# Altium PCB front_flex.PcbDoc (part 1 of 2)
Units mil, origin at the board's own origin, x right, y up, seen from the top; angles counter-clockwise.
Board outline 5591.04 x 1020.3 mil, 4 copper layers (Layer 1 (Top Layer), Layer 2 (PWR), Layer 3 (GND), Layer 4 (Bottom Layer)), stack 21.036 mil thick; 26 components, 44 nets, 150 pads, 87 vias.
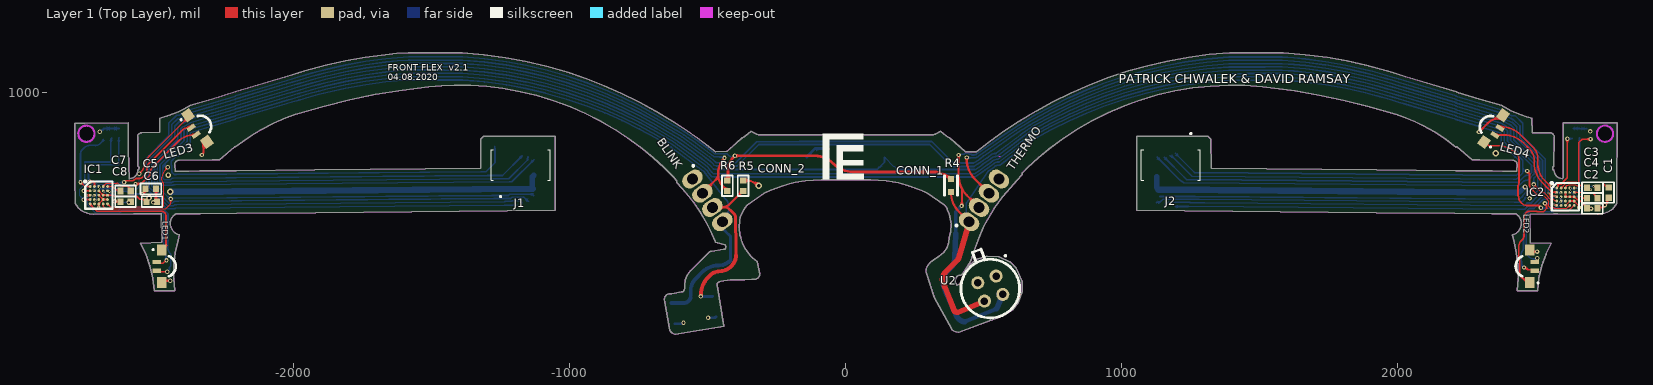
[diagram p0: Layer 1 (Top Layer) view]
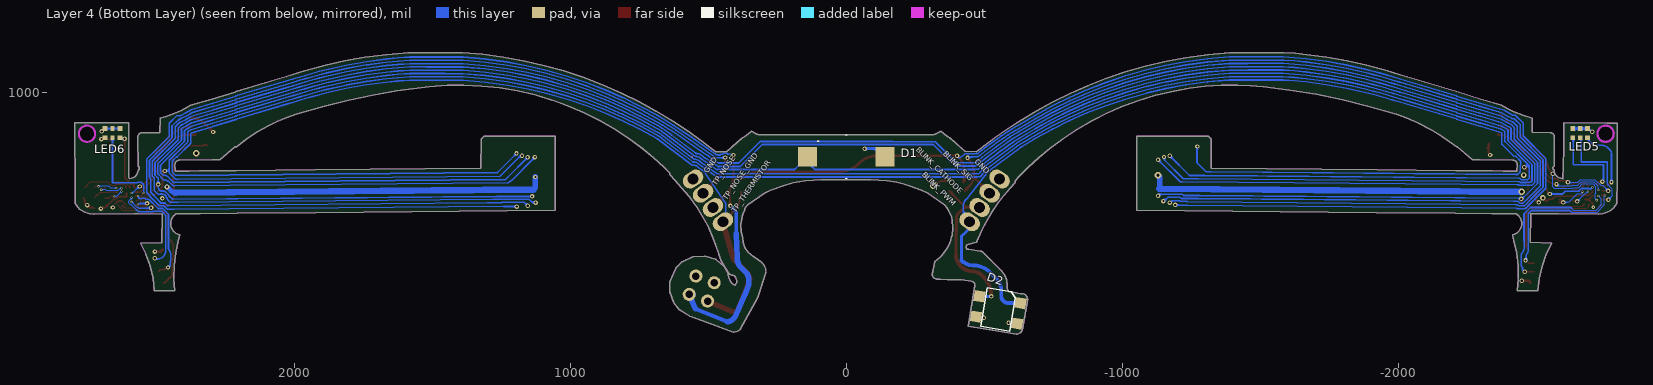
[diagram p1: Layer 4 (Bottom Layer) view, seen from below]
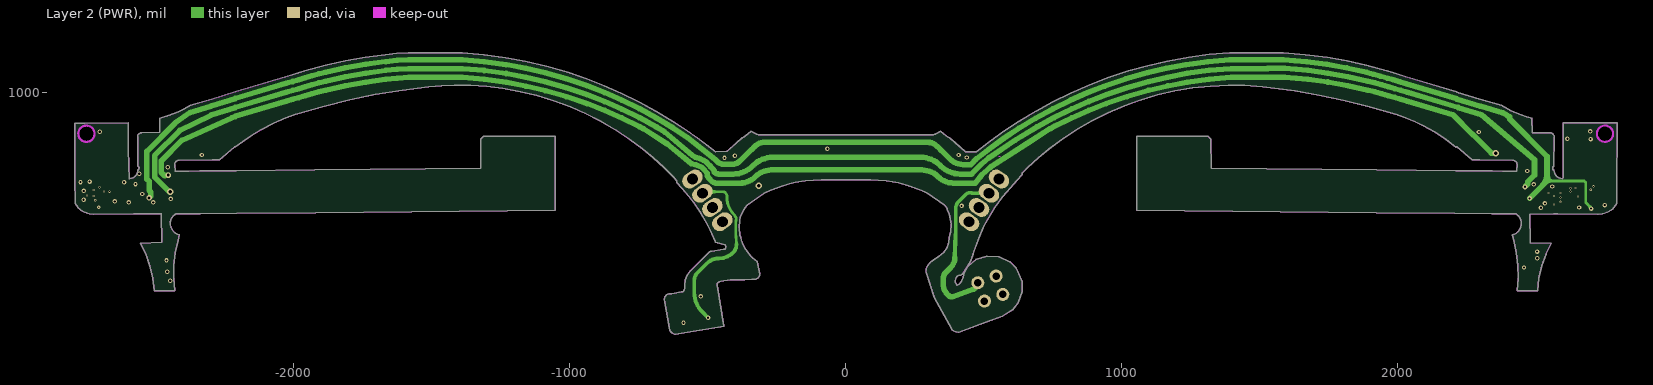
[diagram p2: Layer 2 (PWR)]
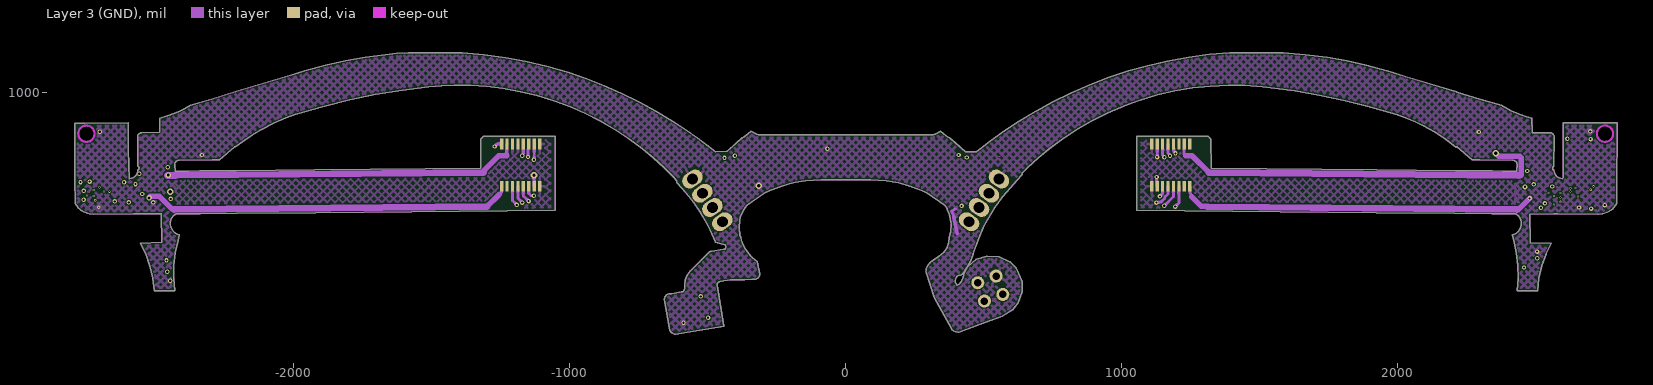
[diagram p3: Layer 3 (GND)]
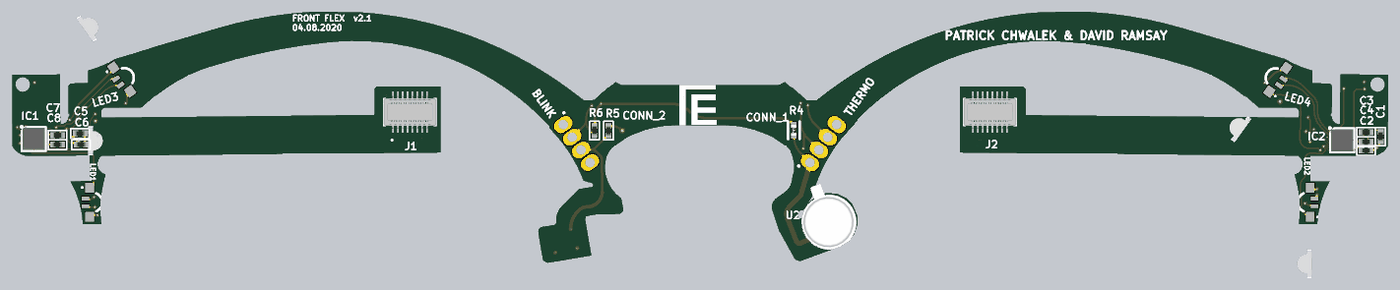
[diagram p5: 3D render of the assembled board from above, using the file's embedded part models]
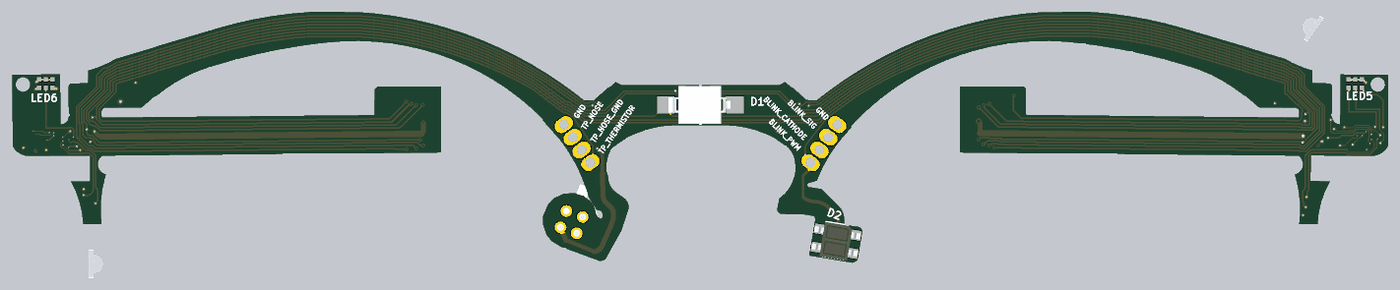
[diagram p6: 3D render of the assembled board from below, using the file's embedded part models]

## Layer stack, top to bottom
Top Solder: solder mask 1, SM-002, Dk 4
Layer 1 (Top Layer): signal copper 0.709
Dielectric 2: prepreg 2.8, PP-006, Dk 4.1
Layer 2 (PWR): signal copper 0.709
Dielectric 1: dielectric 12.6, FR-4, Dk 4.8
Layer 3 (GND): signal copper 0.709
Dielectric 3: prepreg 2.8, PP-006, Dk 4.1
Layer 4 (Bottom Layer): signal copper 0.709
Bottom Solder: solder mask 1, SM-002, Dk 4

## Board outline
570 vertices, not listed, extent -2794.4,125.06 2796.64,1145.35
cut-out: 2745.53,821.61 2750.93,820.83 2756.32,821.06 2761.63,822.28 2766.6,824.41 2771.08,827.44 2774.98,831.26 2778.09,835.71 2780.3,840.67 2781.6,845.91 2781.91,851.34 2781.24,856.73 2779.59,861.89 2777.03,866.65 2773.6,870.91 2769.47,874.41 2764.78,877.13 2762.11,878.23 2759.31,879.05 2753.92,879.8 2748.52,879.61 2743.21,878.39 2738.25,876.22 2733.76,873.19 2729.86,869.37 2726.75,864.92 2724.55,860 2723.25,854.72 2722.93,849.33 2723.6,843.94 2725.26,838.78 2727.82,833.98 2731.24,829.76 2735.38,826.22 2740.06,823.5 2742.74,822.44
cut-out: -2746.95,879.53 -2752.38,879.84 -2755.26,879.57 -2758.13,879.05 -2763.29,877.28 -2768.01,874.65 -2772.18,871.18 -2775.61,866.97 -2778.25,862.24 -2779.98,857.09 -2780.73,851.73 -2780.49,846.3 -2779.27,841.02 -2777.11,836.06 -2774.03,831.57 -2770.22,827.72 -2765.77,824.61 -2760.81,822.4 -2755.53,821.1 -2750.14,820.83 -2747.22,821.06 -2744.35,821.61 -2739.23,823.35 -2734.51,826.02 -2730.33,829.49 -2726.87,833.66 -2724.23,838.43 -2722.5,843.54 -2721.75,848.94 -2721.99,854.33 -2723.25,859.65 -2725.41,864.61 -2728.44,869.09 -2732.26,872.95 -2736.75,876.02 -2741.67,878.27
board region "Layer Stack Region 1": 534 vertices, not listed, extent -2794.4,125.06 2796.64,1145.35
board region "Layer Stack Region 1": -2424.82,715.71 -2380.81,716.14 -2341.51,716.5 -2209.43,717.72 -1923.84,720.31 -1323.01,726.93 -1322.62,728.31 -1322.62,832.13 -1311.87,842.87 -1053.36,843.15 -1053.36,573.35 -1920.92,565.39 -2206.48,562.76 -2340.1,561.53 -2379.43,561.18 -2423.37,560.78 -2425.18,560.77
board region "Layer Stack Region 1": 2429.51,560.75 2380.53,561.18 2341.28,561.53 2207.66,562.76 1922.11,565.39 1054.31,573.35 1054.31,842.87 1312.78,842.87 1323.53,831.85 1324.63,726.22 1326.04,725.79 1925.02,720.31 2210.57,717.72 2342.7,716.5 2382.03,716.14 2430.3,715.75 2432.23,715.74

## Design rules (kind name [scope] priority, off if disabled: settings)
Clearance [All] p1: gap=4 ignorepadtopadclearanceinfootprint=FALSE except(0: Arc-Hole Track-Hole SMDPad-Hole THPad-Hole Via-Hole Fill-Hole Poly-Hole Region-Hole Text-Hole)
DiffPairsRouting [All] p1: maxlimit=10 minlimit=10 mostfreqgap=10 toplayer_minwidth=15 toplayer_maxwidth=15 toplayer_prefwidth=15 midlayer1_minwidth=15 midlayer1_maxwidth=15 midlayer1_prefwidth=15 midlayer2_minwidth=15 midlayer2_maxwidth=15 midlayer2_prefwidth=15 bottomlayer_minwidth=15 bottomlayer_maxwidth=15 bottomlayer_prefwidth=15 substack1={A9119681-F30E-4965-AEFB-5FD7E99CBF57} toplayer_{a9119681-f30e-4965-aefb-5fd7e99cbf57}_minwidth=15 toplayer_{a9119681-f30e-4965-aefb-5fd7e99cbf57}_maxwidth=15 toplayer_{a9119681-f30e-4965-aefb-5fd7e99cbf57}_prefwidth=15 midlayer1_{a9119681-f30e-4965-aefb-5fd7e99cbf57}_minwidth=15 midlayer1_{a9119681-f30e-4965-aefb-5fd7e99cbf57}_maxwidth=15 midlayer1_{a9119681-f30e-4965-aefb-5fd7e99cbf57}_prefwidth=15 midlayer2_{a9119681-f30e-4965-aefb-5fd7e99cbf57}_minwidth=15 midlayer2_{a9119681-f30e-4965-aefb-5fd7e99cbf57}_maxwidth=15 midlayer2_{a9119681-f30e-4965-aefb-5fd7e99cbf57}_prefwidth=15 bottomlayer_{a9119681-f30e-4965-aefb-5fd7e99cbf57}_minwidth=15 bottomlayer_{a9119681-f30e-4965-aefb-5fd7e99cbf57}_maxwidth=15 bottomlayer_{a9119681-f30e-4965-aefb-5fd7e99cbf57}_prefwidth=15 substack2={F6C10761-EC22-4305-87DD-0F5299EFC78A} toplayer_{f6c10761-ec22-4305-87dd-0f5299efc78a}_minwidth=15 toplayer_{f6c10761-ec22-4305-87dd-0f5299efc78a}_maxwidth=15 toplayer_{f6c10761-ec22-4305-87dd-0f5299efc78a}_prefwidth=15 midlayer1_{f6c10761-ec22-4305-87dd-0f5299efc78a}_minwidth=15 midlayer1_{f6c10761-ec22-4305-87dd-0f5299efc78a}_maxwidth=15 midlayer1_{f6c10761-ec22-4305-87dd-0f5299efc78a}_prefwidth=15 midlayer2_{f6c10761-ec22-4305-87dd-0f5299efc78a}_minwidth=15 midlayer2_{f6c10761-ec22-4305-87dd-0f5299efc78a}_maxwidth=15 midlayer2_{f6c10761-ec22-4305-87dd-0f5299efc78a}_prefwidth=15 bottomlayer_{f6c10761-ec22-4305-87dd-0f5299efc78a}_minwidth=15 bottomlayer_{f6c10761-ec22-4305-87dd-0f5299efc78a}_maxwidth=15 bottomlayer_{f6c10761-ec22-4305-87dd-0f5299efc78a}_prefwidth=15 maxuncoupledlength=500
PlaneClearance [All] p1: clearance=8
PlaneConnect GND [InNet('GND')] p1: planeconnectstyle=Direct reliefexpansion=20 reliefentries=4 reliefconductorwidth=10 reliefairgap=10
PlaneConnect [All] p2: planeconnectstyle=Direct reliefexpansion=20 reliefentries=4 reliefconductorwidth=10 reliefairgap=10
PolygonConnect GND_1 [InNet('GND')] p1: thpad.connectstyle=Relief thpad.reliefconductorwidth=10 thpad.reliefentries=4 thpad.polygonreliefangle="90 Angle" thpad.airgapwidth=10 smdpad.connectstyle=Relief smdpad.reliefconductorwidth=10 smdpad.reliefentries=4 smdpad.polygonreliefangle="90 Angle" smdpad.airgapwidth=10 via.connectstyle=Direct via.reliefconductorwidth=10 via.reliefentries=4 via.polygonreliefangle="90 Angle" via.airgapwidth=10
PolygonConnect [All] p2: connectstyle=Relief reliefconductorwidth=10 reliefentries=4 polygonreliefangle="90 Angle" airgapwidth=10
RoutingCorners [All] p1: cornerstyle=Round minsetback=100 maxsetback=100
RoutingVias [All] p1: holewidth=8 width=16 viastyle="Through Hole" minholewidth=4 minwidth=8 maxholewidth=12 maxwidth=24
SolderMaskExpansion [All] p1: expansion=4 istentingtop=FALSE
Width POWER [InNet('3.3V') or InNet('5V') or InNet('BATTERY_1') or InNet('VBAT')] p1: maxlimit=30 minlimit=4 preferedwidth=20 toplayer_prefwidth=8 midlayer1_prefwidth=10 bottomlayer_prefwidth=8 substack1={A9119681-F30E-4965-AEFB-5FD7E99CBF57} substack2={F6C10761-EC22-4305-87DD-0F5299EFC78A} minimp=50.000000 maximp=50.000000 favimp=50.000000
Width [All] p2: maxlimit=10 minlimit=4 preferedwidth=10 toplayer_prefwidth=6 midlayer1_minwidth=10 midlayer2_minwidth=10 bottomlayer_prefwidth=6 substack1={A9119681-F30E-4965-AEFB-5FD7E99CBF57} substack2={F6C10761-EC22-4305-87DD-0F5299EFC78A} minimp=50.000000 maximp=50.000000 favimp=50.000000
26 further rules are at their usual default settings.

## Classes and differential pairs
component class Sch_led: C1 C2 C3 C4 C5 C6 C7 C8 IC1 IC2 J1 J2 LED1 LED2 LED3 LED4 LED5 LED6
component class Sch_front: CONN_1 CONN_2 D1 D2 R4 R5 R6 U2

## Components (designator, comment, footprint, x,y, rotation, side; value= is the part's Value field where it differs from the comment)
C1 "1µF" 0402R 2765.05,638.31 r90 top
C2 "1µF" 0402R 2706.02,581.51 r180 top
C3 "0.47µF" 0402R 2706.01,656.3 r180 top
C4 "0.47µF" 0402R 2706.02,616.93 r180 top
C5 "1µF" 0402R -2518.48,651.43 r180 top
C6 "1µF" 0402R -2514.43,605.63 r180 top
C7 "0.47µF" 0402R -2610.08,643.98 r0 top
C8 "0.47µF" 0402R -2610.08,605.63 r180 top
CONN_1 "THERMO" 4_POS_1MM_HEADER 501.25,610.02 r55 top
CONN_2 "BLINK" 4_POS_1MM_HEADER -501.25,610.02 r305 top
D1 "VBPW34FASR" VBPW34FAS 0,767.67 r180 bottom
D2 "QRE1113GR" *4LEADSMD_QRE1113GR(PRIMARY) -550.53,212.31 r9.5 bottom
IC1 "LP5523TM_NOPB" BGA25C40P5X5_226X226X68 -2706.84,628.81 r0 top
IC2 "LP5523TM_NOPB" BGA25C40P5X5_226X226X68 2608.64,623.29 r0 top
J1 "55560-0168" 555600168 -1178.04,737.95 r0 top
J2 "55560-0168" 555600168 1178.03,737.95 r180 top
LED1 "APFA3010SEKJ3ZGKQBKC" KPFA-3010RGBC-11 -2486.98,371.04 r90 top
LED2 "APFA3010SEKJ3ZGKQBKC" KPFA-3010RGBC-11 2486.98,371.04 r270 top
LED3 "APFA3010SEKJ3ZGKQBKC" KPFA-3010RGBC-11 -2355.09,866.3 r125.5 top
LED4 "APFA3010SEKJ3ZGKQBKC" KPFA-3010RGBC-11 2353.64,865.3 r234.5 top
LED5 "SMLP36RGB2W3R" ROHM-1510-(0604) -2659.41,853.66 r180 bottom
LED6 "SMLP36RGB2W3R" ROHM-1510-(0604) 2659.41,853.66 r180 bottom
R4 "100k" SMD-0402-RES 381.34,664.08 r180 top
R5 "100" 0402R -372.08,662.99 r270 top
R6 "51.1K" 0402R -428.65,662.99 r90 top
U2 "ZTP-135SR" ZTP-135SR 524.02,290.32 r335 top

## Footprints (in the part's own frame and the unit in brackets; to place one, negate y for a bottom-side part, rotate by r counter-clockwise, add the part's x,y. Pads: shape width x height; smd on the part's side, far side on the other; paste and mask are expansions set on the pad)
4_POS_1MM_HEADER [mm]
  oval 1.4x2 hole 1: 1(-2.4,0) 2(-0.8,0) 3(0.8,0) 4(2.4,0)
  silkscreen extent -3.4,0.7 -3.3,0.8
0402R [mm]
  rect 0.559x0.6 smd: 1(-0.48,0) 2(0.48,0)
  silkscreen extent -0.95,-0.5 0.95,0.5, body extent -0.46,-0.25 0.5,0.25, height 0.3
555600168 [mm]
  rect 0.3x1 on Mid1: 1(-1.75,-1.95) 2(-1.75,1.95) 3(-1.25,-1.95) 4(-1.25,1.95) 5(-0.75,-1.95) 6(-0.75,1.95) 7(-0.25,-1.95) 8(-0.25,1.95) 9(0.25,-1.95) 10(0.25,1.95) 11(0.75,-1.95) 12(0.75,1.95) 13(1.25,-1.95) 14(1.25,1.95) 15(1.75,-1.95) 16(1.75,1.95)
  silkscreen extent -2.73,-2.95 2.73,1.42, body extent -2.72,-2.15 2.73,2.15, height 1.16
*4LEADSMD_QRE1113GR(PRIMARY) [mm]
  rect 1x1 smd: A(-1.93,-0.97) C(1.93,0.94) E(-1.93,0.94) K(1.93,-0.97)
  silkscreen extent -1.35,-1.85 1.35,1.75, body extent -2.4,-1.8 2.4,1.8, height 1.85
BGA25C40P5X5_226X226X68 [mil]
  round 10 smd: A1(-31.5,31.5) A2(-15.75,31.5) A3(0,31.5) A4(15.75,31.5) A5(31.5,31.5) B1(-31.5,15.75) B2(-15.75,15.75) B3(0,15.75) B4(15.75,15.75) B5(31.5,15.75) C1(-31.5,0) C2(-15.75,0) C3(0,0) C4(15.75,0) C5(31.5,0) D1(-31.5,-15.75) D2(-15.75,-15.75) D3(0,-15.75) D4(15.75,-15.75) D5(31.5,-15.75) E1(-31.5,-31.5) E2(-15.75,-31.5) E3(0,-31.5) E4(15.75,-31.5) E5(31.5,-31.5)
  silkscreen extent -53,-49 49,53, body extent -44,-44 44,44, height 27
KPFA-3010RGBC-11 [mm]
  rect 1x0.9 smd: 1(1.5,-0.2) 2(-1.5,-0.2)
  rect 0.4x0.8 smd: 3(-0.4,0.25) 4(0.4,0.25)
  silkscreen extent -0.92,-1.5 1.54,0.59, body extent -1.36,-1.55 1.64,-0.05, height 1.02
ROHM-1510-(0604) [mm]
  rect 0.45x0.45 smd: 1(-0.675,-0.425) 3(0.675,-0.425) 4(0.675,0.425) 6(-0.675,0.425)
  rect 0.4x0.45 smd: 2(0,-0.425) 5(0,0.425)
SMD-0402-RES [mm]
  rect 0.55x0.55 smd: 1(0,0.584) 2(0,-0.584)
  silkscreen extent -0.6,-0.9 0.6,0.9, body extent -0.28,-0.57 0.27,0.58, height 0.41
VBPW34FAS [mm] "IR Photodiode SMD (Vive)"
  rect 1.75x1.8 smd: 1(-3.575,0) 2(3.575,0)
  silkscreen extent -2.65,-2 0.08,2, body extent -3.29,-1.95 3.11,1.95, height 1.48
ZTP-135SR [mm]
  round 1.2 hole 0.7: 1(0,1.27) 2(1.27,0) 3(0,-1.27) 4(-1.27,0)
  silkscreen extent -2.9,-2.7 2.7,3.35, body extent -3.24,-2.79 2.74,3.19, height 2.67

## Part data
C1 C2 C5 C6: library part GCM155C71A105KE38D, "CAP CER 1UF 10V X7S 0402", Digi-Key Part Number=490-13409-1-ND, Manufacturer="Murata Electronics North America", Operating Temperature="-55°C ~ 125°C", Package / Case="0402 (1005 Metric)", Ratings=AEC-Q200, Temperature Coefficient=X7S, Tolerance=±10%, Voltage=10V
C3 C4 C7 C8: library part GCM155C71A105KE38D, "CAP CER 0.47UF 10V X7S 0402", Digi-Key Part Number=490-13409-1-ND, Manufacturer="Murata Electronics North America", Operating Temperature="-55°C ~ 125°C", Package / Case="0402 (1005 Metric)", Ratings=AEC-Q200, Temperature Coefficient=X7S, Tolerance=±10%, Voltage=10V
CONN_1 CONN_2: library part 4_pin_1mm_header
D1: "Diode", Manufacturer_Name=Vishay, Mouser Part Number=782-VBPW34FASR, RS Part Number=7689401
D2: "QRE1113 Series 30 V 50 mA Miniature Reflective Object Sensor - SMD-4", Package="SMD-4 ON Semiconductor"
IC1 IC2: "Integrated Circuit", Manufacturer_Name="Texas Instruments", Manufacturer_Part_Number=LP5523TM/NOPB
J1 J2: "Connector", Manufacturer_Name=Molex, Mouser Part Number=538-55560-0168, RS Part Number=7206558P
LED1 LED2 LED3 LED4: "LED", Manufacturer_Name=Kingbright, Mouser Part Number=604-APFA3010SEKJ3ZGK
LED5 LED6: "LED", Manufacturer_Name="ROHM Semiconductor", Mouser Part Number=755-SMLP36RGB2W3R, RS Part Number=1246884
R4: library part ERJ-2GEJ104X, "RES SMD 100K OHM 5% 1/10W 0402", Digi-Key Part Number=P100KJCT-ND, Manufacturer="Panasonic Electronic Components", Operating Temperature="-55°C ~ 155°C", Package / Case="0402 (1005 Metric)", Power (Watts)="0.1W, 1/10W", Supplier Device Package=0402, Temperature Coefficient=±200ppm/°C, Tolerance=±5%
R5: library part Resistor
R6: library part Resistor, "CRCW040251K1FKED"
U2: "Undefined or Miscellaneous", Manufacturer_Name="Amphenol Advanced Sensors", Mouser Part Number=527-ZTP-135SR

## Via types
v1: diameter 16, hole 8, Layer 1 (Top Layer) to Layer 4 (Bottom Layer), tented both sides, 43 vias
v2: diameter 8, hole 4, Layer 1 (Top Layer) to Layer 4 (Bottom Layer), tented both sides, 19 vias
v3: diameter 16, hole 8, Layer 3 (GND) to Layer 4 (Bottom Layer), tented both sides, 17 vias
v4: diameter 24, hole 12, Layer 1 (Top Layer) to Layer 4 (Bottom Layer), tented both sides, 3 vias
v5: diameter 20, hole 10, Layer 1 (Top Layer) to Layer 4 (Bottom Layer), tented both sides, 2 vias
v6: diameter 18, hole 8, Layer 1 (Top Layer) to Layer 4 (Bottom Layer), tented both sides, 1 vias
v7: diameter 12, hole 6, Layer 1 (Top Layer) to Layer 4 (Bottom Layer), tented both sides, 1 vias
v8: diameter 24, hole 12, Layer 3 (GND) to Layer 4 (Bottom Layer), tented both sides, 1 vias

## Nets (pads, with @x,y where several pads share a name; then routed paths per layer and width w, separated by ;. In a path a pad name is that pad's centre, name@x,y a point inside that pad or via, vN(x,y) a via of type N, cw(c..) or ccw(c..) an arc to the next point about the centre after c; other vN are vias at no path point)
3.3V: J1.5 R4.2 R6.2 | length 4799
  Layer 1 (Top Layer) w10: R6.2@-428.65,681.89 ccw(c-434.31,687.55) -426.3,687.55 -426.3,719.92 cw(c-361.88,719.92) -407.44,765.47 v1(-401.49,771.42) -111.65,771.42 cw(c-111.65,677.91) -45.53,744.03 -44.07,742.57 ccw(c26.64,813.28) 26.64,713.28 318.08,713.28 cw(c318.08,623.82) R4.2@381.34,687.08 ; R6.2@-426.39,678.52 R6.2@-424.46,676.59
  Layer 3 (GND) w10: J1.5@-1207.57,661.18 -1207.57,609.07 v3(-1192.04,593.54)
  Layer 4 (Bottom Layer) w6: v3@-1192.04,591.99 -1192.89,592.84 -1236.74,592.84 -2430.07,581.9 -2430.21,581.9 -2431.91,580.19 -2444.01,580.19 -2444.51,579.69 -2460.74,579.69 -2475.35,594.3 -2534.88,653.83 -2534.88,761.79 -2452.92,843.75 -2452.92,890.28 -2424.96,918.24 -2415.31,918.24 -2384.45,936.57 -2296.29,962.47 -2212.03,987.84 -2212.05,989.31 -2027.38,1043.99 -2004.16,1050.86 -1981.48,1057.58 -1958.79,1064.3 -1934.04,1071.43 -1909.34,1078.15 -1884.54,1084.49 -1812.46,1100.67 -1739.75,1113.65 -1667.03,1123.33 -1624.87,1127.45 -1582.61,1130.47 -1520.87,1130.42 -1454.76,1130.33 -1388.64,1130.2 -1308.84,1123.29 -1229.5,1112.41 -1158.68,1099.25 -1088.65,1082.93 -1011.52,1061.06 -935.43,1035.32 -872.62,1010.82 -810.87,983.68 -747.3,952.45 -685.15,918.5 -624.51,881.9 -612.61,876.29 -581.43,857.37 -560.3,843.15 -534.44,824.28 -500.04,798.98 -479.44,782.4 -474.95,779.56 -462.07,778.39 -446.19,778.39 -445.52,779.06 -430.32,779.06 -422.65,771.39 -407.66,763.39
5V: J1.13 J2.14 | length 8474.4
  Layer 3 (GND) w10: v8(-1129.82,701.02) -1129.82,680.69 -1129.74,680.61 -1129.74,662.09 J1.13@-1128.83,661.18 ; v3(1126.77,694.87) 1126.77,681.72 1127.91,680.58 1127.91,662.09 J2.14@1128.82,661.18
  Layer 2 (PWR) w20: v4(-2447.81,640.97) -2451.37,640.97 -2504.88,694.49 -2504.88,771.99 -2413.25,863.62 -2300.83,918.33 -2300.54,918.42 ; -2296.79,919.87 -2212.54,945.24 -2212.55,946.71 -2027.88,1001.39 -2004.67,1008.27 -1981.98,1014.99 -1959.29,1021.71 -1934.54,1028.84 -1909.85,1035.55 -1885.04,1041.9 -1812.96,1058.07 -1740.25,1071.06 -1667.53,1080.74 -1625.37,1084.85 -1583.11,1087.87 -1521.37,1087.82 -1455.26,1087.74 -1389.14,1087.61 -1309.35,1080.7 -1230,1069.81 -1159.18,1056.65 -1089.15,1040.34 -1012.02,1018.46 -935.93,992.73 -873.12,968.22 -811.37,941.09 -747.8,909.86 -685.65,875.9 -655.33,857.6 -556.5,773.72 -544.91,766.19 -526.56,760.81 -517.02,756.2 -503.94,747.65 -491.02,734.73 cw(c-492.99,732.78) -490.22,732.78 -480.87,723.43 cw(c-492.15,712.14) -476.19,712.14 ccw(c-459.9,728.43) -459.9,705.39 -407.7,705.39 ccw(c-407.7,805.39) -336.99,734.68 -335.05,736.62 cw(c-264.34,665.91) -264.34,765.91 271.97,765.91 cw(c271.97,665.91) 342.68,736.62 344.72,734.58 ; 344.75,734.55 ccw(c414.87,804.73) 414.87,705.52 455.96,705.52 492.08,741.64 518.88,763.66 613.79,828.13 693.14,876.03 755.29,909.99 818.86,941.22 880.62,968.35 943.42,992.86 1019.52,1018.59 1096.65,1040.47 1166.68,1056.78 1237.5,1069.94 1316.84,1080.83 1396.64,1087.74 1462.75,1087.87 1528.87,1087.96 1590.61,1088 1632.87,1084.98 1675.03,1080.87 1747.74,1071.19 1820.45,1058.21 1892.54,1042.03 1917.34,1035.68 1942.04,1028.97 1966.79,1021.84 1989.48,1015.12 2012.16,1008.4 2035.37,1001.52 2220.04,946.84 2220.03,945.37 2304.29,920 2496.4,756.74 2496.4,701.92 2471.36,676.87 2471.36,668.85 v6@2464.72,662.21
  Layer 4 (Bottom Layer) w18: 2430.83,637.81 ccw(c2430.83,660.71) 2447.03,644.52 v6(2461.72,659.21)
  Layer 4 (Bottom Layer) w20: v4(-2447.81,640.97) -2438.32,640.97 v4@-2436.54,639.19 ; -1135.17,652.17 -1135.17,695.67 v8(-1129.82,701.02) ; v3(1126.77,694.87) 1126.77,690.21 1126.58,690.02 1126.58,657.15 1134.03,649.7
  Layer 4 (Bottom Layer) w25: v4@-2442.86,640.18 -1135.17,652.17 ; 1134.03,649.7 2430.83,637.81
BATTERY_1: J1.4 J2.3 | length 7986.3
  Layer 3 (GND) w10: v5@-2458.08,700.29 -2456.75,701.61 v5(-2455.44,701.61) ; -1228.81,771.84 -1228.81,794.65 -1228.16,795.3 -1228.16,813.82 J1.4@-1227.26,814.72 ; 1226.31,793.66 1226.31,777.34 1231.92,771.73
  Layer 3 (GND) w20: -1309.05,719.78 -1256.99,771.84 -1228.81,771.84 ; 1231.92,771.73 1254.59,771.73 1315.99,710.33 ; v4(2356.48,780.71) 2366.67,770.53 2442.16,770.53 2448.38,764.32 2448.38,702.31 2445.12,699.05
  Layer 3 (GND) w25: v5@-2458.08,700.29 -2428.97,700.29 ; -2422.55,701 -1312.36,711.18 ; 1315.99,710.33 2437.99,700.05
  Layer 2 (PWR) w20: v5(-2455.44,701.61) -2465.99,701.61 -2468.3,699.3 -2480.5,711.5 -2480.5,753.43 -2406.86,827.08 -2225.73,909.08 -2212.55,913.04 -2212.57,914.51 -2027.9,969.19 -2004.69,976.07 -1982,982.79 -1959.31,989.51 -1934.56,996.64 -1909.86,1003.35 -1885.06,1009.7 -1812.98,1025.88 -1740.27,1038.86 -1667.55,1048.54 -1625.39,1052.65 -1583.13,1055.67 -1521.39,1055.62 -1455.28,1055.54 -1389.16,1055.41 -1309.36,1048.5 -1230.02,1037.61 -1159.2,1024.45 -1089.17,1008.14 -1012.04,986.26 -935.95,960.53 -873.14,936.02 -811.39,908.89 -747.82,877.66 -732.28,869.17 -646.69,814.44 -558.92,742.19 -543.33,738.91 -519.08,728.85 -502.39,708.22 ccw(c-474.55,708.22) -494.24,688.53 -485.86,680.15 ccw(c-467.23,698.78) -467.23,672.44 -384.6,672.44 ccw(c-384.6,754.84) -326.33,696.57 cw(c-269.38,639.62) -269.38,720.16 275.78,720.16 cw(c275.78,636.68) 334.75,695.77 cw(c275.78,636.68) 334.82,695.71 ccw(c390.69,751.58) 390.69,672.57 469.98,672.57 493.33,702.12 525.19,730.93 654.19,814.57 739.77,869.3 755.31,877.79 818.88,909.02 880.64,936.15 943.44,960.66 1019.54,986.39 1096.67,1008.27 1166.7,1024.58 1237.52,1037.74 1316.86,1048.63 1396.66,1055.54 1462.77,1055.67 1528.88,1055.76 1590.62,1055.8 1632.88,1052.78 1675.04,1048.67 1747.76,1038.99 1820.47,1026.01 1892.56,1009.83 1917.36,1003.48 1942.06,996.77 1966.81,989.64 1989.49,982.92 2012.18,976.2 2035.39,969.32 2200.08,920.56 2270.47,850.17 ; 2272.91,849.59 2272.91,848.71 2340.14,781.48 2355.72,781.48 v4(2356.48,780.71)
BLINK_CATHODE: CONN_2.3 D2.K R5.2 | length 587.2
  Layer 1 (Top Layer) w4: CONN_2.3@-483.18,584.21 CONN_2.3@-448.37,584.21 ; R5.2@-374.11,643.25 cw(c-372.08,641.23) -373.07,643.92 cw(c-372.08,641.23) R5.2@-372.08,644.09
  Layer 1 (Top Layer) w8: CONN_2.3@-448.37,584.21 ccw(c-448.37,620.95) -436.24,586.27 ccw(c-448.37,620.95) -422.39,594.98 R5.2@-374.11,643.25
  Layer 1 (Top Layer) w10: v1(-525.03,261.81) v1@-525.03,265.74 ; -436.24,586.27 cw(c-457.05,534.75) -417.76,574.04 -403.54,559.83 cw(c-413.1,550.27) -399.58,550.27 -399.58,493.16 cw(c-405.24,487.51) -397.24,487.51 -397.24,411.02
  Layer 1 (Top Layer) w14: v1@-525.03,265.74 cw(c-430.11,265.74) -497.23,332.86 -492.01,338.09 cw(c-455.79,301.87) -455.79,353.09 ccw(c-455.79,406.73) -417.86,368.8 -412.52,374.14 ccw(c-449.4,411.02) -397.24,411.02
  Layer 4 (Bottom Layer) w10: v1(-525.03,261.81) -483.59,261.81 ccw(c-483.59,264.21) D2.K@-481.89,262.51
BLINK_PWM: CONN_2.4 D2.A J1.2 | length 4132.4
  Layer 1 (Top Layer) w6: CONN_2.4@-442.08,525.52 ccw(c-442.08,532.53) -437.13,527.57 CONN_2.4@-432.41,532.3
  Layer 3 (GND) w10: v3(-1272.3,805.2) -1262.78,814.72 J1.2@-1246.94,814.72
  Layer 4 (Bottom Layer) w6: -2375.27,853.83 -2375.27,811.97 -2378.2,811.97 -2420.87,769.3 -2426.87,769.3 -2444.26,751.91 -2444.26,738.68 -2442.09,736.51 -2442.09,716.8 ccw(c-2431.24,716.8) -2438.91,709.13 -2433.57,703.78 -2426.99,703.78 -1321.89,713.92 -1303.42,713.92 -1271.24,746.1 -1271.24,793.42 -1271.48,793.66 -1271.48,804.38 v3(-1272.3,805.2) ; -2375.27,855.33 -2298.01,878.29 -2297.73,878.37 ; -2296.29,878.47 -2212.03,903.84 -2212.05,905.31 -2027.38,959.99 -2004.16,966.86 -1981.48,973.58 -1958.79,980.3 -1934.04,987.43 -1909.34,994.15 -1884.54,1000.49 -1812.46,1016.67 -1739.75,1029.65 -1667.03,1039.33 -1624.87,1043.45 -1582.61,1046.47 -1520.87,1046.42 -1454.76,1046.33 -1388.64,1046.2 -1308.84,1039.29 -1229.5,1028.41 -1158.68,1015.25 -1088.65,998.93 -1011.52,977.06 -935.43,951.32 -872.62,926.82 -810.87,899.68 -747.3,868.45 -685.15,834.5 -633.35,803.23 -515,715.73 -435.84,615.43 cw(c-464.96,586.31) -423.78,586.31 -423.78,582.43 cw(c-487.88,582.43) CONN_2.4@-442.56,537.11 ; CONN_2.4@-436.79,520.99 -436.79,531.38 CONN_2.4@-415.14,553.03
  Layer 4 (Bottom Layer) w10: -562.56,256.5 ccw(c-588.5,264.26) -561.43,264.26 ; CONN_2.4@-447.05,532.61 -447.05,509.76 -436.96,499.66 ; -436.96,499.62 -417.4,480.06 -417.4,392.41
  Layer 4 (Bottom Layer) w14: D2.A@-631.78,237.43 -587.92,237.43 ccw(c-587.92,263.68) -569.35,245.12 ccw(c-588.5,264.26) -562.56,256.5 ; -561.43,264.26 -561.43,291.72 cw(c-495.16,279.4) -542.82,327.06 -519.94,349.94 cw(c-461.34,291.34) -461.34,374.21 ccw(c-461.34,436.36) -417.4,392.41
BLINK_SIG: CONN_2.2 D2.C J1.7 R6.1 | length 4748.1
  Layer 1 (Top Layer) w8: CONN_2.2@-519.31,635.82 -470.64,684.49 ccw(c-491.16,705.04) -462.12,705.04 ; v1(-439.31,764.06) ccw(c-384.24,708.99) -462.12,708.99 -462.12,705.04 ; R6.1@-428.65,644.09 -429.46,644.09 -438.46,653.09 -438.46,653.91 -445.49,660.93 cw(c-405.34,701.08) -462.12,701.08 -462.12,705.04
  Layer 3 (GND) w10: J1.7@-1187.89,661.18 -1187.89,617.67 v3(-1172.24,602.02)
  Layer 2 (PWR) w10: CONN_2.2@-519.31,635.82 cw(c-506.06,622.56) -506.06,641.31 -443.64,641.31 cw(c-443.64,631.09) -436.42,638.31 cw(c-451.01,623.72) -430.37,623.72 -430.37,621.25 ccw(c-342.13,621.25) -404.52,558.85 -404.61,558.77 cw(c-424.12,539.25) -396.52,539.25 -396.52,538.22 ccw(c-392.62,534.32) -398.14,534.32 -398.14,494.61 -395.89,449.75
  Layer 2 (PWR) w14: -502.08,382.18 -538.5,345.76 ccw(c-513.9,321.16) -548.69,321.16 -548.69,275.89 ccw(c-448.69,275.89) -519.4,205.18 v1(-498.66,184.43) ; -502.07,382.19 cw(c-459.88,339.98) -459.88,399.66 ccw(c-459.88,473.48) -407.69,421.28 ccw(c-436.16,449.75) -395.89,449.75
  Layer 4 (Bottom Layer) w6: -2297.73,950.37 -2298.01,950.29 -2375.27,927.33 -2393.36,916.85 -2412,907.34 -2413.04,906.3 -2420.57,906.3 -2442.09,884.78 -2442.09,840.44 -2524.88,757.64 -2524.88,657.97 -2513.73,646.82 -2504.49,637.57 -2456.6,589.69 -2456.1,590.19 -2436.05,590.19 -2431.68,594.57 -2424.27,594.57 -1235.74,605.47 -1234.2,607.01 -1209.55,607.01 -1208.26,608.31 -1198.48,608.31 -1198.25,608.54 -1180.99,608.54 -1174.48,602.02 v3(-1172.24,602.02) -1172.24,600.43 -1172.89,600.43 v3@-1173.36,600.91 ; -2296.29,950.47 -2212.03,975.84 -2212.05,977.31 -2027.38,1031.99 -2004.16,1038.86 -1981.48,1045.58 -1958.79,1052.3 -1934.04,1059.43 -1909.34,1066.15 -1884.54,1072.49 -1812.46,1088.67 -1739.75,1101.65 -1667.03,1111.33 -1624.87,1115.45 -1582.61,1118.47 -1520.87,1118.42 -1454.76,1118.33 -1388.64,1118.2 -1308.84,1111.29 -1229.5,1100.41 -1158.68,1087.25 -1088.65,1070.93 -1011.52,1049.06 -935.43,1023.32 -872.62,998.82 -810.87,971.68 -747.3,940.45 -685.15,906.5 -624.51,869.9 -614.19,864.37 -599.21,855.32 -585.74,847.02 -569.63,835.97 -551.73,823.87 -528.75,807.05 -502.31,787.12 -478.74,769.2 -458.79,767.27 v1@-442.39,767.14
  Layer 4 (Bottom Layer) w10: v1(-498.66,184.43) -478.95,184.43 ccw(c-478.95,197.81) D2.C@-469.48,188.35
EXPANSION_INT: J1.12 J2.11 | length 8291.9
  Layer 3 (GND) w10: v3(-1151.42,767.1) -1151.42,794.18 -1149.42,796.18 -1149.42,813.82 J1.12@-1148.52,814.72 ; J2.11@1148.5,814.72 1148.5,774.12 1155,767.62 v3(1155,766)
  Layer 4 (Bottom Layer) w6: -2297.73,902.37 -2298.01,902.29 -2375.27,879.33 -2393.36,868.85 -2398.09,864.12 -2398.09,826.36 -2484.88,739.57 -2484.88,679.45 -2480.73,675.3 -2467.31,675.3 -2466.62,674.61 -2443.04,674.61 -2439.56,678.1 -2436.42,678.1 -1276.47,688.62 -1220.64,688.62 -1153.14,756.13 -1153.14,762.56 -1150.62,765.07 -1150.62,766.31 v3(-1151.42,767.1) ; -2296.29,902.47 -2212.03,927.84 -2212.05,929.31 -2027.38,983.99 -2004.16,990.86 -1981.48,997.58 -1958.79,1004.3 -1934.04,1011.43 -1909.34,1018.15 -1884.54,1024.49 -1812.46,1040.67 -1739.75,1053.65 -1667.03,1063.33 -1624.87,1067.45 -1582.61,1070.47 -1520.87,1070.42 -1454.76,1070.33 -1388.64,1070.2 -1308.84,1063.29 -1229.5,1052.41 -1158.68,1039.25 -1088.65,1022.93 -1011.52,1001.06 -935.43,975.32 -872.62,950.82 -810.87,923.68 -747.3,892.45 -685.15,858.5 -624.51,821.9 -617.18,817.07 -509.59,738.46 -499.2,729.45 -494.01,723.42 -484.79,711.31 -479.4,705.92 -468.69,706.03 467.53,706.03 486.5,719.59 508.54,734.91 527.35,748.72 527.93,749.3 cw(c551.95,725.28) 551.95,759.25 655,837.18 664.91,844.49 670.27,848.66 673.34,851.07 684.89,857.72 747.04,891.68 810.61,922.91 872.36,950.04 935.17,974.55 1011.26,1000.28 1088.39,1022.16 1158.42,1038.47 1229.24,1051.63 1308.58,1062.51 1388.38,1069.42 1454.5,1069.56 1520.61,1069.64 1582.35,1069.69 1624.61,1066.67 1666.77,1062.56 1739.49,1052.88 1812.2,1039.89 1884.28,1023.71 1909.08,1017.37 1933.78,1010.66 1958.53,1003.53 1981.22,996.81 2003.91,990.08 2027.12,983.21 2211.79,928.53 2211.77,927.06 2296.03,901.69 ; v3(1155,766) 1228.02,692.98 1235.37,685.49 2434.22,674.61 ccw(c2434.22,683.38) 2440.42,677.18 2459.8,696.56 cw(c2470.15,686.21) 2470.15,700.85 ccw(c2470.15,714.77) 2480,704.93 2485.38,710.3 2485.38,737.62 2398.62,824.38 2398.62,862.13 2393.89,866.86 2375.8,877.34 ; 2296.26,901.39 2296.55,901.3 2373.8,878.34
GND: C1.1 C2.1 C5.1 C6.1 CONN_1.4 CONN_2.1 D1.2 D2.E IC1.C3 IC1.D4 IC1.D5 IC1.E3 IC2.D4 IC2.D5 IC2.E3 J1.6 J1.8 J1.15 J1.16 J2.15 J2.16 LED1.2 LED2.2 LED3.2 LED4.2 LED5.4 LED5.5 LED5.6 LED6.4 LED6.5 LED6.6 R5.1 U2.1 | length 868.6
  Layer 1 (Top Layer) w4: v7(-2706.96,585.42) -2706.96,597.18 -2706.84,597.3 IC1.D4@-2691.09,613.06 IC1.D5@-2675.34,613.06 ; IC1.C3@-2706.75,628.91 -2706.75,628.72 -2691.88,613.85 IC1.D4@-2691,613.85 ; LED1.2@-2481,310.09 -2478.75,307.83 LED1.2@-2475.93,307.83 ; R5.1@-372.08,681.89 R5.1@-361.14,681.89 ; LED2.2@2473.75,428.37 LED2.2@2475.56,426.56 ; IC2.E3@2608.62,591.81 2608.62,592.99 2610.79,595.16 2612.18,596.55 2613.19,596.55 2619.64,602.99 2619.64,604.01 2623.19,607.56 IC2.D5@2640.13,607.55 ; IC2.D5@2640.13,607.55 2655.83,591.85 2655.83,586.37 v1(2658.13,584.07)
  Layer 1 (Top Layer) w6: v1@-2510.44,602.72 v1@-2507.53,605.63 ; v1(-2509.54,602.72) v1@-2509.54,603.62 ; C6.1@-2499.58,605.69 -2499.53,605.63 C6.1@-2498.6,606.56 ; C2.1@2724.92,581.51 2730.97,584.16 2741.89,584.16 v1(2750.76,593.03) 2753.47,593.03 2757.89,597.45 2758.39,597.45 2759.88,598.94 2759.88,614.25 C1.1@2765.05,619.42
  Layer 1 (Top Layer) w8: C6.1@-2499.58,605.69 C5.1@-2499.58,651.43 ; v1(-2333.09,774.3) -2333.09,777.04 -2327.49,782.64 LED3.2@-2327.49,813.5 ; R5.1@-361.14,681.89 cw(c-361.14,617.37) v4(-315.51,662.99) ; v1(2294.91,857.82) 2326.66,889.57 cw(c2370.99,845.24) LED4.2@2370.99,907.93
  Layer 1 (Top Layer) w10: LED1.2@-2479.1,311.99 -2478.95,311.99 -2471.84,319.1 -2471.72,318.97 -2448,318.97 v1(-2447.81,318.78) ; LED2.2@2479.1,430.1 2484.97,424.23 v1(2505.87,424.23)
  Layer 3 (GND) w10: 392.46,549.45 384.04,571.02 397.67,579.26
  Layer 3 (GND) w13: 392.46,549.45 403.77,488.61
  Layer 4 (Bottom Layer) w6: LED6.4@2636.76,870.39 LED6.5@2659.41,870.39 ; LED6.5@2662.87,870.18 2685.17,870.18 2685.52,869.83 2685.98,870.3 LED6.6@2685.98,870.39
  Layer 4 (Bottom Layer) w8: v1(-2703.42,858.47) -2702.42,858.47 -2695.55,865.34 -2692.86,865.34 -2688,870.2 LED5.6@-2634.85,870.2
  Layer 4 (Bottom Layer) w10: D2.E@-619.37,163.27 -596.53,163.27 ccw(c-596.53,173.24) -589.48,166.19 cw(c-588.54,165.25) -588.54,166.58 v1(-587.92,166.58) ; D1.2@-140.75,767.67 -140.75,768.25 -111.3,797.7 -66.86,797.7 v1(-66.26,797.09)
  other v1: 2698.42,860.08
I2C_SCL: IC1.E5 IC2.E5 J1.10 J2.9 | length 8801.1
  Layer 1 (Top Layer) w4: IC1.E5@-2675.34,597.3 -2665.33,587.3 -2486.9,587.3 -2486.56,587.64 -2474.64,587.64 -2470.95,591.33 -2470.95,666.06 ccw(c-2482.64,666.06) -2474.37,674.33 cw(c-2463.22,685.48) -2478.99,685.48 -2478.99,693.13 cw(c-2396.15,669.36) v1(-2457.09,730.3) ; 2513.54,629.26 2526.97,629.26 2537.49,618.74 2537.49,618.61 2548.7,607.4 2548.7,588.02 2564.08,572.64 2619.77,572.64 2627.93,580.8 2628.94,580.8 2635.38,587.24 2635.38,588.26 2638.94,591.81 IC2.E5@2640.12,591.81
  Layer 1 (Top Layer) w6: v1(2470.38,716.52) ccw(c2476.46,716.52) 2472.16,712.21 2478.11,706.26 2478.11,665.71 ccw(c2494.66,665.71) 2482.95,654.01 2503.57,633.4 ccw(c2513.54,643.37) 2513.54,629.26
  Layer 3 (GND) w10: v3(-1172.25,771.73) -1172.25,773.35 -1168.2,777.4 J1.10@-1168.2,814.72 ; J2.9@1168.19,814.72 1168.19,780.51 1175.35,773.35 v3(1175.35,771.73)
  Layer 4 (Bottom Layer) w6: v1@-2459.79,730.3 -2464.92,735.43 -2474.88,735.43 ; -2297.73,890.37 -2298.01,890.29 -2375.27,867.33 -2386.42,860.87 -2386.42,823.12 -2387.19,823.12 -2474.88,735.43 ; -2296.29,890.47 -2212.03,915.84 -2212.05,917.31 -2027.38,971.99 -2004.16,978.86 -1981.48,985.58 -1958.79,992.3 -1934.04,999.43 -1909.34,1006.15 -1884.54,1012.49 -1812.46,1028.67 -1739.75,1041.65 -1667.03,1051.33 -1624.87,1055.45 -1582.61,1058.47 -1520.87,1058.42 -1454.76,1058.33 -1388.64,1058.2 -1308.84,1051.29 -1229.5,1040.41 -1158.68,1027.25 -1088.65,1010.93 -1011.52,989.06 -935.43,963.32 -872.62,938.82 -810.87,911.68 -747.3,880.45 -685.15,846.5 -624.51,809.9 -510.51,725.59 -501.89,717.16 -495.65,708.03 -484.87,695.5 -474.2,694.7 469.14,694.7 469.65,695.2 491.17,710.08 534.11,740.93 cw(c554,721.04) 554,749.16 555.58,749.16 654.81,824.28 678.08,841.93 680.91,842.95 684.89,845.72 747.04,879.68 810.61,910.91 872.36,938.04 935.17,962.55 1011.26,988.28 1088.39,1010.16 1158.42,1026.47 1229.24,1039.63 1308.58,1050.51 1388.38,1057.42 1454.5,1057.56 1520.61,1057.64 1582.35,1057.69 1624.61,1054.67 1666.77,1050.56 1739.49,1040.88 1812.2,1027.89 1884.28,1011.71 1909.08,1005.37 1933.78,998.66 1958.53,991.53 1981.22,984.81 2003.91,978.08 2027.12,971.21 2211.79,916.53 2211.77,915.06 2296.03,889.69 ; v3(-1172.25,771.73) -1243.65,700.32 -1298.42,700.32 -2436.49,689.89 -2441.91,689.89 -2447.18,684.61 -2462.48,684.61 -2463.16,685.3 -2469.11,685.3 -2474.88,691.07 -2474.88,735.43 ; v3(1175.35,771.73) 1177.26,769.82 1182.45,769.82 1255.06,697.22 2420.56,686.53 2425.72,686.53 ccw(c2425.72,699.22) 2434.7,690.25 2453.4,708.95 2453.4,717.42 2453.62,717.64 ; 2296.26,889.39 2296.55,889.3 2373.8,866.34 ; 2375.8,865.34 2386.95,858.88 2386.95,821.64 2431.28,777.31 2431.54,777.31 2453.62,755.23 2453.62,717.64 ; v1(2470.38,716.52) 2469.25,717.64 2453.62,717.64
I2C_SDA: IC1.E4 IC2.E4 J1.11 J2.12 | length 8977.7
  Layer 1 (Top Layer) w4: IC1.E4@-2691.09,597.31 -2691.09,589.06 -2681.32,579.3 -2483.58,579.3 -2483.24,579.64 -2463.73,579.64 -2446.41,596.96 v1(-2446.41,615.19) ; v1(2493.36,667.76) 2519.52,641.6 ccw(c2525.71,647.79) 2525.71,639.03 cw(c2525.71,628.32) 2533.29,635.9 2544.24,624.95 cw(c2541.22,621.93) 2545.49,622.06 cw(c2541.22,621.93) 2545.49,621.93 2556.7,610.72 2556.7,591.34 2567.4,580.64 2613.25,580.64 IC2.E4@2624.38,591.8 IC2.E4@2624.37,591.81
  Layer 3 (GND) w10: J1.11@-1148.52,661.18 -1148.27,660.94 -1148.27,634.62 -1140.68,627.02 v3(-1130.02,627.02) ; v3(1138.93,624.27) 1148.5,633.85 J2.12@1148.5,661.18
  Layer 4 (Bottom Layer) w6: v1@-2448.96,615.24 -2504.88,671.17 -2504.88,747.85 -2421.09,831.65 -2421.09,874.25 -2412,883.34 -2393.36,892.85 -2375.27,903.33 -2298.01,926.29 -2297.73,926.37 ; v1(-2446.41,615.19) -2446.41,615.4 -2444.65,617.16 -2435.72,617.16 -1282.57,627.63 -1220.65,627.63 -1220.65,629.38 -1218.2,631.84 -1209,631.92 -1201.01,631.99 ; -2296.29,926.47 -2212.03,951.84 -2212.05,953.31 -2027.38,1007.99 -2004.16,1014.86 -1981.48,1021.58 -1958.79,1028.3 -1934.04,1035.43 -1909.34,1042.15 -1884.54,1048.49 -1812.46,1064.67 -1739.75,1077.65 -1667.03,1087.33 -1624.87,1091.45 -1582.61,1094.47 -1520.87,1094.42 -1454.76,1094.33 -1388.64,1094.2 -1308.84,1087.29 -1229.5,1076.41 -1158.68,1063.25 -1088.65,1046.93 -1011.52,1025.06 -935.43,999.32 -872.62,974.82 -810.87,947.68 -747.3,916.45 -685.15,882.5 -624.51,845.9 -599.64,831.18 -570.65,810.7 -526.68,779.34 -491.01,752.29 -481.74,743.89 -477.21,737.85 -469.67,734.79 -393.65,734.39 -315.65,812.39 304.62,812.39 384.16,732.85 465.34,732.85 485.75,745.94 511.86,763.79 517.24,766.89 520.23,769.87 cw(c544.93,745.16) 544.93,780.1 633.56,846.87 638.4,850.97 651.22,860.8 659.19,866.53 664.18,869.2 668.58,871.77 669.8,872.68 684.89,881.72 747.04,915.68 810.61,946.91 872.36,974.04 935.17,998.55 1011.26,1024.28 1088.39,1046.16 1158.42,1062.47 1229.24,1075.63 1308.58,1086.51 1388.38,1093.42 1454.5,1093.56 1520.61,1093.64 1582.35,1093.69 1624.61,1090.67 1666.77,1086.56 1739.49,1076.88 1812.2,1063.89 1884.28,1047.71 1909.08,1041.37 1933.78,1034.66 1958.53,1027.53 1981.22,1020.81 2003.91,1014.08 2027.12,1007.21 2211.79,952.53 2211.77,951.06 2296.03,925.69 ; -1209,631.99 -1201.01,631.99 ; v3(-1130.02,627.02) -1135.59,632.59 -1201.01,631.99 ; v3(1138.93,624.27) 1266.24,624.27 2441.52,613.6 2448.98,621.05 2450.04,621.05 2453.6,624.62 2453.6,627.58 2468.25,642.22 2469.88,642.22 ; 2296.26,925.39 2296.55,925.3 2373.8,902.34 ; 2375.8,901.34 2393.89,890.86 2412.53,881.35 2421.62,872.26 2421.62,829.66 2505.38,745.9 2505.38,702.02 2493.36,690 v1(2493.36,667.76) 2493.36,658.4 cw(c2475.57,658.4) 2488.15,645.82 cw(c2483.65,650.32) 2483.65,643.96 2475.03,643.96 ccw(c2475.03,635.44) 2469.88,642.22 ; 2469.01,641.46 cw(c2475.03,635.44) 2469.88,642.22
IMU_INT: J1.9 J2.10 | length 8642
  Layer 3 (GND) w10: J1.9@-1168.2,661.18 -1168.2,626.27 v3(-1149.34,607.41) ; v3(1126.26,602) 1127.4,603.15 1141.85,603.15 1155.93,617.23 1155.93,621.23 1168.19,633.5 J2.10@1168.19,661.18
  Layer 4 (Bottom Layer) w6: -2297.73,938.37 -2298.01,938.29 -2375.27,915.33 -2393.36,904.85 -2412,895.34 -2415.05,895.34 -2432.09,878.3 -2432.09,836.3 -2514.88,753.5 -2514.88,662.12 -2453,600.23 -2452.67,600.23 -2452.62,600.19 -2440.2,600.19 -2433.74,606.65 -2416.99,606.65 -1275.71,617.01 -1213.7,617.01 -1208.96,621.75 ; -2296.29,938.47 -2212.03,963.84 -2212.05,965.31 -2027.38,1019.99 -2004.16,1026.86 -1981.48,1033.58 -1958.79,1040.3 -1934.04,1047.43 -1909.34,1054.15 -1884.54,1060.49 -1812.46,1076.67 -1739.75,1089.65 -1667.03,1099.33 -1624.87,1103.45 -1582.61,1106.47 -1520.87,1106.42 -1454.76,1106.33 -1388.64,1106.2 -1308.84,1099.29 -1229.5,1088.41 -1158.68,1075.25 -1088.65,1058.93 -1011.52,1037.06 -935.43,1011.32 -872.62,986.82 -810.87,959.68 -747.3,928.45 -685.15,894.5 -624.51,857.9 -593.5,839.8 -544.25,804.99 -493.27,767.27 -479.05,755.42 -469.65,746.39 -398.65,746.39 -322.65,822.39 -168.61,822.39 -167.41,823.6 312.41,823.6 390.39,745.61 464.25,745.61 465.02,746.38 481.68,756.02 500.68,771.23 526.51,788.69 608.66,846.53 616.72,851.98 629.32,859.97 652.02,873.85 658.47,878.09 667.91,883.45 684.89,893.72 747.04,927.68 810.61,958.91 872.36,986.04 935.17,1010.55 1011.26,1036.28 1088.39,1058.16 1158.42,1074.47 1229.24,1087.63 1308.58,1098.51 1388.38,1105.42 1454.5,1105.56 1520.61,1105.64 1582.35,1105.69 1624.61,1102.67 1666.77,1098.56 1739.49,1088.88 1812.2,1075.89 1884.28,1059.71 1909.08,1053.37 1933.78,1046.66 1958.53,1039.53 1981.22,1032.81 2003.91,1026.08 2027.12,1019.21 2211.79,964.53 2211.77,963.06 2296.03,937.69 ; -1208.96,621.88 -1166.91,622.27 -1152.05,607.41 v3(-1149.34,607.41) ; v3(1126.26,602) 1127.06,602.8 1138.67,602.8 1150.14,614.27 1262.1,614.27 1262.92,613.45 1281.51,613.45 2422.79,603.09 2444.31,603.09 ccw(c2444.31,616.94) 2454.1,607.14 2459.55,612.59 ccw(c2453.54,618.59) 2462.03,618.59 2463.97,620.53 cw(c2471.84,620.53) 2466.27,626.09 2467.6,627.42 ; 2296.26,937.39 2296.55,937.3 2373.8,914.34 ; 2375.8,913.34 2393.89,902.86 2412.53,893.35 2415.58,893.35 2432.62,876.31 2432.62,834.31 2515.38,751.56 2515.38,697.88 2508.36,690.86 2508.36,646.1 2507.29,645.03 2507.29,644.76 2495.32,632.78 2485.44,632.78 2485.35,632.87 2479.63,632.87 ccw(c2479.63,620.15) 2473.66,631.38 ccw(c2473.66,626.34) 2470.09,629.9 2468.41,628.22
LED_LEFT_FRONT_B: IC1.A1 LED5.3 | length 254.9
  Layer 1 (Top Layer) w4: v1(-2773.09,676.3) -2757.09,660.3 IC1.A1@-2738.33,660.3
  Layer 4 (Bottom Layer) w6: v1(-2773.09,676.3) -2773.09,781.27 ; -2772.98,781.27 cw(c-2758.68,781.27) -2768.79,791.38 -2759.6,800.57 cw(c-2738.7,779.68) -2738.7,809.22 -2738.7,809.3 -2720.07,809.3 ; LED5.3@-2691.34,830.5 cw(c-2701.43,830.5) -2694.3,823.36 -2700.5,817.15 cw(c-2720.07,836.73) -2716.36,809.3 ; -2720.07,809.3 -2716.36,809.3 ; -2720.07,809.3 -2720.07,809.05 ccw(c-2720.07,836.73) -2716.36,809.3
LED_LEFT_FRONT_G: IC1.A2 LED5.1 | length 308.2
  Layer 1 (Top Layer) w4: IC1.A2@-2722.58,660.3 -2722.58,673.55
  Layer 1 (Top Layer) w6: v1(-2740.11,678.11) -2727.15,678.11 -2722.58,673.55
  Layer 4 (Bottom Layer) w6: v1(-2740.11,678.11) -2743.45,678.11 -2744.09,677.47 -2744.09,739.3 -2634.51,739.3 -2634.51,823.56 ; -2634.29,822.74 -2634.29,836.93 LED5.1@-2632.84,836.93
LED_LEFT_FRONT_R: IC1.D1 LED5.2 | length 357.4
  Layer 1 (Top Layer) w4: v1(-2762.09,612.3) -2761.33,613.05 IC1.D1@-2738.33,613.06
  Layer 4 (Bottom Layer) w4: v1(-2762.09,612.3) -2776.09,626.3 -2776.09,650.51 -2759.09,667.51
  Layer 4 (Bottom Layer) w6: -2759.09,667.51 -2759.09,669.08 -2758.09,670.08 -2758.09,749.3 -2663.09,749.3 -2663.09,832.56 LED5.2@-2663.54,832.56 ; LED5.2@-2659.41,832.56 LED5.2@-2659.41,836.93
LED_LEFT_SIDE_B: IC1.C1 LED1.4 | length 550.5
  Layer 1 (Top Layer) w4: v2@-2748.75,628.35 IC1.C1@-2738.78,628.35
  Layer 1 (Top Layer) w6: v2(-2749.3,627.8) v2@-2748.75,628.35 ; IC1.C1@-2738.78,628.35 IC1.C1@-2738.33,628.8 ; LED1.4@-2493.64,382.63 -2474.04,382.63 -2464.12,392.55 v1(-2461.42,392.55)
  Layer 4 (Bottom Layer) w4: v2@-2747.09,625.58 -2747.09,593.3 -2719.09,565.3 -2630.09,565.3 -2622.09,573.3
  Layer 4 (Bottom Layer) w6: v2(-2749.3,627.8) v2@-2747.09,625.58 ; -2622.09,573.3 -2482.63,573.3 -2471.09,561.75 -2471.09,461.3 ; -2471.28,458.85 -2471.28,430.71 ccw(c-2446.2,430.71) -2463.93,412.97 -2463.93,395.45 v1@-2468.09,391.3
